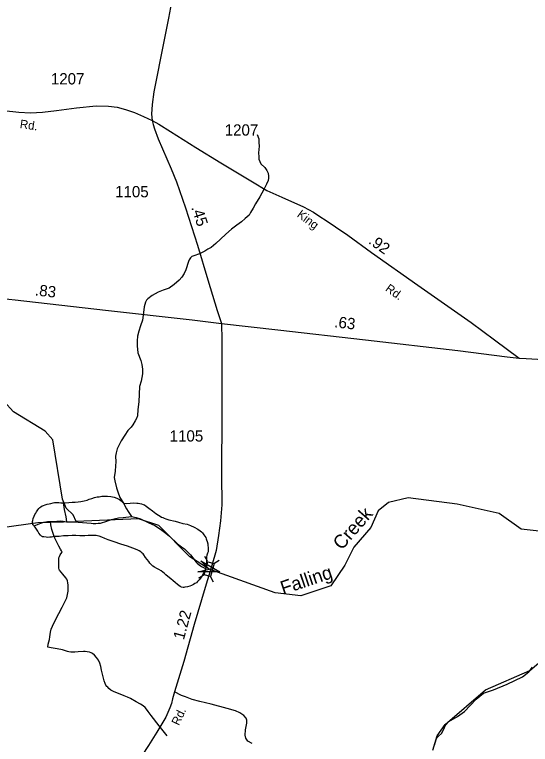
# Model space of a CAD drawing. Extents: x 2206922 to 2357709, y 510027 to 673830.
# Drawn here: x 2230128 to 2235843, y 557602 to 565687 of the extents above; entities that cross this region are included whole.
import ezdxf

# ---------------------------------------------------------------- set-up
doc = ezdxf.new("R2010")
doc.units = 0
for name, color, linetype in [('Exist Hydrographic Creek Single Shore', 7, 'Continuous'), ('Exist Hydrographic Creek Single Shore Label', 7, 'Continuous'), ('Exist Hydrographic Misc Water Feature', 7, 'Continuous'), ('Exist Road Non-System Type 51', 7, 'Continuous'), ('Exist Road Primary US Attributed', 7, 'Continuous'), ('Exist Road Primary US Mileage Hundredths English Label', 7, 'Continuous'), ('Exist Road Secondary Mileage Hundredths English Label', 7, 'Continuous'), ('Exist Road Secondary Structure Standard Bridge Attributed CELL', 7, 'Continuous'), ('Exist Road Secondary Structure Standard Bridge CELL', 7, 'Continuous'), ('Exist Road Secondary Type 51 Attributed', 7, 'Continuous'), ('Exist Road Secondary Type 51 Label', 7, 'Continuous'), ('Exist Road Secondary Type 51 Number Label', 7, 'Continuous')]:
    doc.layers.add(name, color=color, linetype=linetype)

msp = doc.modelspace()

# ---------------------------------------------------------------- linework, layer by layer
at = {"layer": 'Exist Hydrographic Creek Single Shore'}
for points in [[(2236912.4, 559319.9), (2236626.3, 559643.8), (2236266.2, 559864.2), (2235940.2, 559962.7), (2235740.3, 559986.4), (2235497.3, 560158.6), (2235030.2, 560263.1), (2234488.2, 560333.1), (2234272.3, 560281.7), (2234156.3, 560188.9), (2234074.2, 560003.6), (2233885.2, 559787.7), (2233786.1, 559586.4), (2233630.3, 559359.9), (2233298.3, 559248.5), (2233014.1, 559280.5), (2232284.4, 559543.8), (2232070.3, 559680), (2231725.2, 560028.1), (2231500.2, 560101.5), (2230809.2, 560069.6)], [(2228194.2, 558990.8), (2228891.1, 559314.6), (2228989.1, 559473.3), (2229045.1, 559773.9), (2229144.2, 559880.1), (2229509.2, 560043.3), (2229851.2, 559987.2), (2230384.1, 560058.4), (2230809.2, 560069.6)], [(2234761.2, 557536.5), (2234809.3, 557696.1), (2234900.2, 557822.3), (2235347.2, 558206.8), (2235836.2, 558420), (2236085.2, 558631.4)]]:
    msp.add_lwpolyline(points, dxfattribs=at)
at = {"layer": 'Exist Hydrographic Misc Water Feature'}
for points in [[(2232814.6, 564358.8), (2232832.6, 564309.1), (2232835.3, 564270.9), (2232838, 564230.8), (2232830.4, 564154.9), (2232832.6, 564112.8), (2232834.9, 564084.9), (2232844.9, 564061.1), (2232857.2, 564035.3), (2232899.5, 563993.6), (2232923.5, 563961.6), (2232936, 563931.7), (2232942.3, 563897.9), (2232940.5, 563873.9), (2232936.4, 563850.2), (2232920.8, 563809.9), (2232889.6, 563747.7), (2232846, 563669.2), (2232797, 563589), (2232773, 563542.7), (2232741.8, 563492.7), (2232728.1, 563466.4), (2232684.2, 563428), (2232640.9, 563389.9), (2232591.1, 563353.2), (2232531.4, 563308.7), (2232467.4, 563254.2), (2232410, 563198), (2232358.6, 563149.4), (2232306.9, 563107.3), (2232269.2, 563087.1), (2232235.1, 563066.7), (2232177.7, 563038), (2232113.9, 563015.6), (2232092, 563005.6), (2232076.4, 562991.3), (2232062.5, 562971.1), (2232054.5, 562951.2), (2232024.9, 562859.1), (2232005.5, 562818.7), (2231981.9, 562778.8), (2231950.1, 562746.3), (2231896.6, 562698), (2231841, 562657.7), (2231775.4, 562633.2), (2231717.6, 562612.7), (2231651.5, 562574), (2231604.2, 562539.8), (2231590, 562523.6), (2231576.5, 562501.4), (2231564.6, 562449.7), (2231557.2, 562387.5), (2231544.1, 562301.5), (2231522.2, 562239.1), (2231504.9, 562181.2), (2231487.7, 562123.1), (2231484, 562072.9), (2231484.2, 562018.9), (2231492.6, 561939), (2231525.6, 561853.3), (2231537.7, 561809.3), (2231544.5, 561757.6), (2231544.7, 561705.7), (2231529.3, 561627.7), (2231511.9, 561567.5), (2231503.7, 561397.6), (2231494.3, 561313.4), (2231488.7, 561241.3), (2231476.8, 561213.5), (2231465.1, 561187.3), (2231437.5, 561143.2), (2231417.6, 561115), (2231381.7, 561078.6), (2231348.7, 561028.4), (2231309.1, 560963.9), (2231281.6, 560913.7), (2231263.6, 560877.8), (2231252.1, 560833.7), (2231246.4, 560793.7), (2231249, 560731.6), (2231247.2, 560689.7), (2231241.6, 560627.7), (2231232.4, 560559.7), (2231238.8, 560523.5), (2231257.2, 560445.7), (2231271.8, 560398.1), (2231294.1, 560336.3), (2231334.5, 560272.6)], [(2230809.2, 560069.6), (2230775.1, 560145.7), (2230699.1, 560219.4), (2230657.2, 560318.6), (2230551.2, 560976.7), (2230467.2, 561073.5), (2230116.1, 561287.3), (2230007.2, 561404.3), (2229903.1, 561845.8), (2229850.2, 562270), (2229655.2, 562608.5), (2229419.1, 562915), (2229059.1, 563230.6), (2228766, 563344.8), (2228475.1, 563314.5), (2227453.1, 562990.8), (2227178.1, 563006.2), (2226636.2, 563141.8), (2226242.1, 563389.2)], [(2230667.1, 560279.2), (2230687, 560279.1), (2230729.2, 560281.6), (2230764.9, 560284), (2230798.7, 560286.2), (2230832.8, 560288.4), (2230862.7, 560292.7), (2230898.6, 560299.1), (2230930.6, 560309.3), (2230954.4, 560317.4), (2230984.5, 560327.5), (2231014, 560336), (2231042.1, 560344.3), (2231064.3, 560346.3), (2231094.2, 560352.7), (2231126, 560352.7), (2231155.9, 560351.1), (2231194.5, 560347.3), (2231230.2, 560339.5), (2231260.1, 560328.1), (2231288.4, 560314.1), (2231308.7, 560300.5), (2231334.5, 560272.6)], [(2230343.3, 560024.8), (2230337.2, 560030.6), (2230331.4, 560034.7), (2230328.7, 560042.4), (2230326.7, 560050.4), (2230326.9, 560058.5), (2230326.7, 560070.3), (2230328.7, 560082.5), (2230334.5, 560104.4), (2230346.2, 560130.6), (2230352.1, 560148.8), (2230362, 560164.7), (2230372, 560178.6), (2230386, 560198.8), (2230397.4, 560214.9), (2230407.7, 560227.2), (2230419.6, 560235.1), (2230431.5, 560243), (2230447.5, 560249.1), (2230467.2, 560255.5), (2230489.1, 560261.9), (2230511.5, 560265.9), (2230530.7, 560271.9), (2230554.9, 560276.3), (2230568.7, 560280.3), (2230583, 560282.6), (2230596.8, 560280.5), (2230616.8, 560280.8), (2230640.6, 560278.8), (2230667.1, 560279.2)], [(2230667.1, 560279.2), (2230677.3, 560205.1), (2230693.9, 560121.5), (2230702.8, 560067.5)], [(2231334.5, 560272.6), (2231364.5, 560271), (2231406.9, 560275.1), (2231440.3, 560277.3), (2231480.5, 560275.8), (2231498.4, 560273.9), (2231516.4, 560269.9), (2231532.4, 560266.3), (2231550.7, 560260.3), (2231566.6, 560254.7), (2231584.7, 560242.6), (2231614.6, 560219), (2231657.3, 560189.1), (2231691.5, 560161.6), (2231723.5, 560141.8), (2231741.8, 560129.7), (2231755.5, 560119.9), (2231771.5, 560114.3), (2231783.4, 560106.4), (2231802, 560100.3), (2231836.1, 560090.7), (2231905.8, 560073.3), (2231942.1, 560063.8), (2231992.1, 560050.2), (2232038.1, 560040.4), (2232076.2, 560026.6), (2232118.2, 560009.2), (2232156.8, 559987.6), (2232184.5, 559967.6), (2232197, 559955.6), (2232208.9, 559945.7), (2232216.7, 559934), (2232225.3, 559924.1), (2232235.3, 559910.1), (2232245.6, 559892.3), (2232251.5, 559880.1), (2232255.4, 559868.1), (2232262, 559848.5), (2232267.7, 559824.5), (2232270, 559802.2), (2232272, 559786.5), (2232272.4, 559768.6), (2232272.4, 559750.4), (2232271, 559736.4), (2232266.7, 559720.4), (2232258.7, 559696.5), (2232255, 559676.4), (2232253, 559656.4), (2232253.4, 559620.3), (2232251.9, 559584.4), (2232248.2, 559566.3), (2232244.1, 559550.3)], [(2231334.5, 560272.6), (2231369.2, 560212.6), (2231387.4, 560181.1), (2231423.5, 560125.4)], [(2230343.3, 560024.8), (2230416.9, 560053), (2230450.8, 560065.3), (2230492.4, 560070), (2230526.8, 560072.1)], [(2230526.8, 560072.1), (2230594.7, 560076.5), (2230632.4, 560078.9), (2230666.9, 560073.3), (2230702.8, 560067.5)], [(2230566, 559904.4), (2230539.3, 559982.2), (2230528.9, 560036.1), (2230526.8, 560072.1)], [(2230702.8, 560067.5), (2230833, 560062.4), (2230976.9, 560051.7), (2230998.7, 560050), (2231026.7, 560050.2), (2231052.6, 560052.4), (2231078.6, 560052.6), (2231102.6, 560060.7), (2231128.5, 560068.9), (2231178.5, 560085.3), (2231202.3, 560093.5), (2231232.2, 560099.9), (2231277.7, 560110.1), (2231329.8, 560116.8), (2231423.5, 560125.4)], [(2231423.5, 560125.4), (2231476, 560115.9), (2231521.7, 560100), (2231608.5, 560061), (2231682.3, 560025.5), (2231742.8, 559988), (2231803.3, 559942.4), (2231843.7, 559908.8), (2231931.8, 559823.7), (2231978, 559792), (2232010.2, 559768.5), (2232042.8, 559736.8), (2232077, 559702.8), (2232117.4, 559651.3), (2232137.7, 559623.5), (2232149.6, 559609.5), (2232171.6, 559591.6), (2232199.6, 559574), (2232244.1, 559550.3)], [(2230566, 559904.4), (2230538.1, 559898), (2230516.2, 559896.1), (2230494, 559895.8), (2230476, 559897.7), (2230452.2, 559899.7), (2230444, 559899.7), (2230436.2, 559901.3), (2230431.9, 559903.5), (2230426.1, 559907.2), (2230421.8, 559911.2), (2230413.6, 559921.3), (2230397.9, 559943.2), (2230385.5, 559964.8), (2230369.3, 559986.8), (2230355.2, 560006.8), (2230343.3, 560024.8)], [(2231817.6, 557697.7), (2231730.7, 557809), (2231641.7, 557920.2), (2231609.3, 557966), (2231589.2, 557993.7), (2231573.2, 558011.6), (2231552.9, 558027.6), (2231523, 558047.1), (2231474.4, 558074.7), (2231412.2, 558110), (2231378, 558124.1), (2231341.9, 558139.7), (2231277.7, 558165.2), (2231229.5, 558184.6), (2231193.7, 558204.3), (2231173.4, 558222.3), (2231159.6, 558234.2), (2231151, 558243.9), (2231139.3, 558259.9), (2231130.7, 558277.8), (2231118.8, 558307.6), (2231106.3, 558363.4), (2231092.2, 558423.6), (2231083.5, 558463.4), (2231071, 558501.3), (2231056.7, 558535.2), (2231034.9, 558564.8), (2231012.6, 558588.8), (2230992.5, 558608.5), (2230974.7, 558616.5), (2230958.3, 558622.2), (2230930.2, 558628.1), (2230908, 558629.7), (2230890.2, 558629.6), (2230832.4, 558627.4), (2230796.3, 558625.1), (2230774.5, 558622.7), (2230750.3, 558624.8), (2230728.4, 558628.5), (2230712.6, 558630.1), (2230680.4, 558643.8), (2230660.1, 558649.7), (2230600, 558659.6), (2230534.2, 558672.8), (2230496.1, 558678.5), (2230501.4, 558710.5), (2230513.5, 558764.7), (2230517.2, 558792.5), (2230524.6, 558844.5), (2230534.6, 558878.7), (2230546.3, 558912.7), (2230571.7, 558968.8), (2230616.8, 559053.3), (2230654.6, 559121.4), (2230685.7, 559182), (2230705.6, 559224), (2230715.3, 559263.9), (2230720.8, 559297.9), (2230722.7, 559343.9), (2230722.4, 559365.8), (2230718.3, 559392), (2230713.8, 559413.7), (2230705.8, 559432), (2230695.6, 559447.7), (2230661.3, 559489.4), (2230624.8, 559531), (2230621.2, 559541.3), (2230618.7, 559555), (2230618.7, 559585), (2230617.9, 559669.1), (2230619.9, 559676.9), (2230623.6, 559683.2), (2230633.7, 559701.1), (2230651.7, 559727.2), (2230653.6, 559733), (2230649, 559745.1), (2230637.1, 559765.1), (2230619.1, 559797.1), (2230574, 559886.6), (2230566, 559904.4)], [(2232244.1, 559550.3), (2232235.9, 559526.3), (2232218.9, 559490), (2232202.9, 559466.1), (2232186.9, 559443.8), (2232171.3, 559423.8), (2232155.4, 559407.5), (2232141.6, 559393.4), (2232125.4, 559383.3), (2232109.8, 559373.5), (2232087.7, 559363), (2232067.6, 559355.1), (2232044.2, 559346.9), (2232015.7, 559342.6), (2232004, 559340.4), (2231993.8, 559340.3), (2231976.1, 559344.1), (2231961.8, 559349.9), (2231933.5, 559372), (2231905.2, 559395.8), (2231883.5, 559413.3), (2231857.4, 559435), (2231826.9, 559463.2), (2231805.1, 559480.7), (2231788.5, 559496.6), (2231768.8, 559510.4), (2231752.4, 559524.3), (2231726.4, 559540), (2231702.2, 559550.1), (2231678.2, 559565.9), (2231660.2, 559577.5), (2231639.6, 559595.2), (2231627.8, 559611.2), (2231613.4, 559627.2), (2231597.4, 559651.1), (2231579.4, 559672.8), (2231559.3, 559702.6), (2231551.3, 559712.8), (2231541, 559720.4), (2231526.9, 559734.3), (2231507, 559746.2), (2231486.5, 559758.3), (2231438.7, 559777.6), (2231380.5, 559797.4), (2231306.4, 559820.7), (2231232.2, 559846.1), (2231163.9, 559867.3), (2231127.8, 559882.9), (2231093.8, 559899), (2231065.7, 559908.5), (2231047.7, 559912.5), (2231031.7, 559916), (2230989.4, 559918), (2230941.4, 559915.5), (2230906, 559911.1), (2230851.8, 559912.8), (2230805.7, 559914.5), (2230765.9, 559916), (2230720.2, 559913.6), (2230670, 559911.4), (2230619.9, 559906.8), (2230566, 559904.4)], [(2234779.2, 557592), (2234800.5, 557656.2), (2234808.1, 557674.1), (2234823.9, 557694.4), (2234857.7, 557722.5), (2234879.3, 557764.7), (2234902.8, 557816.7), (2234940.8, 557855.2), (2235034.3, 557912), (2235111.8, 557966.5), (2235179.3, 558034.9), (2235242.2, 558103.7), (2235323.8, 558170.1), (2235433.7, 558207), (2235586.7, 558268.3), (2235756.3, 558349.7), (2235825.8, 558404.2), (2235865, 558456.6)]]:
    msp.add_lwpolyline(points, dxfattribs=at)
at = {"layer": 'Exist Road Non-System Type 51'}
msp.add_lwpolyline([(2232761.7, 557611.6), (2232711.5, 557639.2), (2232691.1, 557671), (2232682.4, 557704.4), (2232687.6, 557764.4), (2232700.6, 557837.3), (2232699.3, 557871.2), (2232694.1, 557892), (2232669.2, 557920.8), (2232624.8, 557952.4), (2232576.8, 557972), (2232483.2, 558000.8), (2232307.4, 558049), (2232179.9, 558078.9), (2232093.9, 558099.8), (2232021, 558129.7), (2231978.1, 558144), (2231901.3, 558183.1)], dxfattribs=at)
at = {"layer": 'Exist Road Primary US Attributed'}
for points in [[(2228103, 562213.5), (2228773.7, 562483), (2228907.2, 562538), (2229039, 562571), (2229142.6, 562591.9), (2229232.5, 562606.6), (2229332.5, 562607.4), (2229430.5, 562602.2), (2229512.4, 562596.8), (2229636.5, 562581.9), (2229786.6, 562563), (2229920.7, 562548.1), (2230132.8, 562525.9), (2231135.2, 562414.2), (2232095.7, 562304), (2232421.8, 562264.6)], [(2235717.5, 561881.7), (2235797.4, 561876.3), (2235921.4, 561869.4), (2235985.5, 561863.9), (2236025.5, 561864.3), (2236121.4, 561872.9), (2236372.1, 561897), (2237497.5, 562035.1), (2237708.4, 562058.1), (2237884.8, 562073.5), (2238331.5, 562096.5), (2239531.7, 562165.6), (2240434.8, 562238.5), (2240969.6, 562298.2), (2241503, 562344.6), (2241984.5, 562386.4)], [(2232421.8, 562264.6), (2233046, 562195.8), (2234014.5, 562083.7), (2235039, 561964.2), (2235587.4, 561894.5), (2235717.5, 561881.7)]]:
    msp.add_lwpolyline(points, dxfattribs=at)
at = {"layer": 'Exist Road Secondary Structure Standard Bridge Attributed CELL'}
msp.add_lwpolyline([(2232191, 559634.1), (2232402.2, 559512.2), (2232158.3, 559512.2), (2232284.4, 559543.8)], close=True, dxfattribs=at)
at = {"layer": 'Exist Road Secondary Structure Standard Bridge CELL'}
for p, q in [((2232269.7, 559625.3), (2232235.5, 559685.2)), ((2232336.2, 559607), (2232396.2, 559641.2)), ((2232169.5, 559445.5), (2232229.4, 559479.6)), ((2232331.6, 559401), (2232297.5, 559460.9))]:
    msp.add_line(p, q, dxfattribs=at)
msp.add_lwpolyline([(2232229.4, 559479.6), (2232269.4, 559625.3), (2232337.4, 559606.7), (2232297.5, 559460.9)], close=True, dxfattribs=at)
at = {"layer": 'Exist Road Secondary Type 51 Attributed'}
for points in [[(2231876.1, 565887.1), (2231832, 565647.3), (2231750, 565241.7), (2231699.7, 564979.7), (2231671.3, 564831.4), (2231653.7, 564691), (2231646, 564585.5), (2231653.7, 564512.6)], [(2227750.3, 564923.5), (2228413.6, 564871.4), (2228960.8, 564787.3), (2229545.3, 564700.1), (2230003, 564624.9), (2230175.5, 564605.7), (2230304, 564599.9), (2230435.7, 564605.5), (2230593.4, 564624.7), (2230813.2, 564654.4), (2231032.8, 564676.2), (2231168.9, 564673.3), (2231264.8, 564660.1), (2231355.1, 564636.9), (2231457.3, 564601.6), (2231555.9, 564556.8), (2231653.7, 564512.6)], [(2231653.7, 564512.6), (2231726.6, 564474.3), (2231854.8, 564391.1), (2232135, 564215.3), (2232413, 564046.5), (2232763.8, 563833.6), (2232921, 563737.6), (2233089.7, 563662.8), (2233330.8, 563555.5), (2233440.6, 563497.8), (2233500, 563457.6), (2233592.1, 563400), (2233684.5, 563334.4), (2233821.2, 563241.6), (2234081, 563052.8), (2234597.3, 562688.1), (2235186.4, 562275.1), (2235445.9, 562085.3), (2235717.5, 561881.7)], [(2231653.7, 564512.6), (2231663.3, 564468.5), (2231676.7, 564422.5), (2231717, 564312.2), (2231862.7, 563979.3), (2231922.1, 563835.5), (2232019.6, 563546.8), (2232152.9, 563134), (2232268.1, 562749.2), (2232370.6, 562410.2), (2232421.8, 562264.6)], [(2232421.8, 562264.6), (2232423.3, 562080.9), (2232423.8, 561275.1), (2232421.5, 560585.6), (2232424.3, 560257.6), (2232407.6, 560077.6), (2232387, 559915.5), (2232359.5, 559751.4), (2232314, 559582.1), (2232307, 559558.9)], [(2232307, 559558.9), (2232241, 559338.5), (2232116.1, 558930.8), (2232004.5, 558521), (2231901.3, 558183.1), (2231879.1, 558105.6), (2231866.1, 558055.5), (2231847.9, 558006), (2231825.8, 557953.9), (2231803.6, 557905), (2231704.7, 557738.3), (2231611, 557590.5), (2231477.9, 557387.2), (2231319.4, 557146.3), (2231182.7, 556932), (2231049.9, 556732.7), (2230943.1, 556563.4), (2230887.1, 556460.5), (2230841.6, 556356.3), (2230822.1, 556295.7), (2230801.2, 556216.9), (2230789.5, 556171.3)]]:
    msp.add_lwpolyline(points, dxfattribs=at)

# ---------------------------------------------------------------- texts
at = {"layer": 'Exist Hydrographic Creek Single Shore Label'}
for s, rotation, p in [('Creek', 48.78802, (2233753, 559746.4)), ('Falling', 18.54894, (2233102.6, 559259))]:
    msp.add_text(s, height=150, rotation=rotation, dxfattribs=at).set_placement(p)
at = {"layer": 'Exist Road Primary US Mileage Hundredths English Label'}
for s, rotation, p in [('.83', 353.64166, (2230349.3, 562576.3)), ('.63', 353.39764, (2233665.5, 562223.4))]:
    msp.add_text(s, height=125, rotation=rotation, dxfattribs=at).set_placement(p)
at = {"layer": 'Exist Road Secondary Mileage Hundredths English Label'}
for s, rotation, p in [('.45', 287.89571, (2232084.1, 563550.5)), ('.92', 324.7653, (2234040.3, 563158)), ('1.22', 74.77433, (2232003, 558753.2))]:
    msp.add_text(s, height=125, rotation=rotation, dxfattribs=at).set_placement(p)
at = {"layer": 'Exist Road Secondary Type 51 Label'}
for s, rotation, p in [('Rd.', 351.97123, (2230181.3, 564430.7)), ('King', 323.38161, (2233248.9, 563454.3)), ('Rd.', 324.479, (2234227.9, 562633)), ('Rd.', 64.48271, (2231947, 557804.2))]:
    msp.add_text(s, height=95, rotation=rotation, dxfattribs=at).set_placement(p)
at = {"layer": 'Exist Road Secondary Type 51 Number Label'}
for s, p in [('1207', (2230529.7, 564913.5)), ('1207', (2232455.9, 564346.3)), ('1105', (2231241.2, 563663)), ('1105', (2231846.1, 560956.8))]:
    msp.add_text(s, height=125, dxfattribs=at).set_placement(p)

doc.saveas('drawing.dxf')
